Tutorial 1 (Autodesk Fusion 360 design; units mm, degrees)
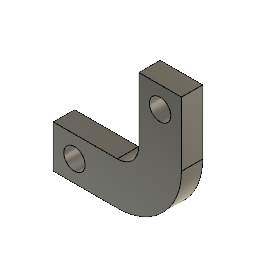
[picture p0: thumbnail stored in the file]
sketch "Sketch1" plane through (0, 0, 0) normal (0, 1, 0) x axis (1, 0, 0)
  line L1 (18, 0) -> (0, 0)
  line L2 (36, -36) -> (36, -18)
  line L3 (18, -12) -> (0, -12)
  line L4 (24, -36) -> (24, -18)
  line L5 (0, 0) -> (0, -12)
  line L6 (36, -36) -> (24, -36)
  arc A1 centre (18, -18) radius 18 clockwise from (18, 0) to (36, -18)
  arc A2 centre (18, -18) radius 6 clockwise from (18, -12) to (24, -18)
  circle C1 centre (6, -6) radius 3
  circle C2 centre (30, -30) radius 3
  point P1 (0, 0)
  point P2 (0, 0)
  point P12 (0, 0)
  point P4 (18, 0)
  point P3 (36, -36)
  point P5 (36, -18)
  point P13 (6, -6)
  point P14 (30, -30)
  coincident P1 P2
  horizontal L1
  perpendicular L1 L2
  tangent L1 A1
  tangent L2 A1
  coincident P1 P12
  perpendicular L1 L5
  perpendicular L2 L6
  equal C1 C2
  dimension "d1" radius A1 = 18
  dimension "d2" = 12
  dimension "d5" distance P2 P4 = 18
  dimension "d6" distance P3 P5 = 18
  dimension "d7" distance L5 P13 = 6
  dimension "d8" distance L1 P13 = 6
  dimension "d9" distance L2 P14 = 6
  dimension "d10" distance L6 P14 = 6
  dimension "d11" diameter C2 = 6
extrude "Extrude1" new body sketch "Sketch1" distance 6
